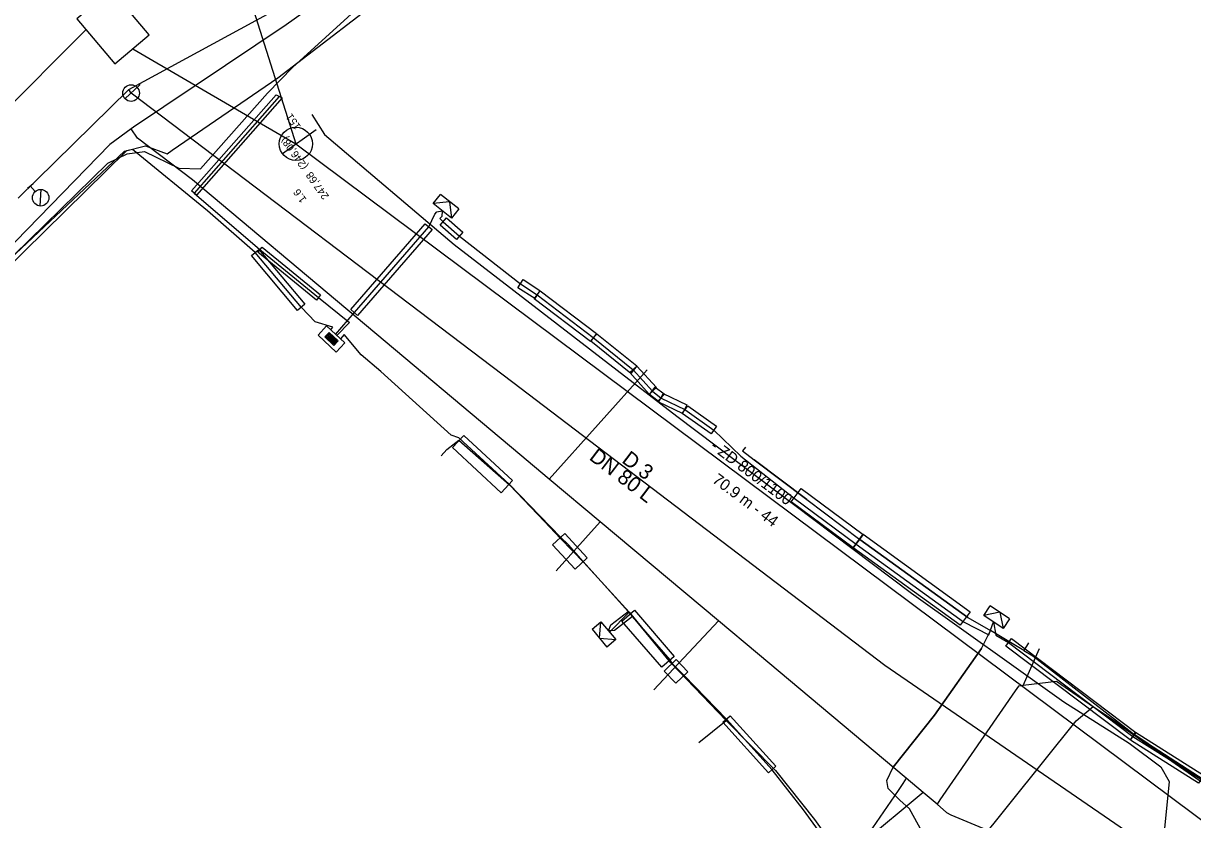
# Model space of a CAD drawing. Extents: x -600636 to -600148, y -1203980 to -1203569.
# Drawn here: x -600384.3 to -600313.9, y -1203678.1 to -1203630.1 of the extents above; entities that cross this region are included whole.
import ezdxf

# ---------------------------------------------------------------- set-up
doc = ezdxf.new("R2010")
doc.units = 0
for name, color, linetype in [('Cetin zam průběh', 7, 'Continuous'), ('EON objekty', 7, 'Continuous'), ('EON podzemní NN', 7, 'Continuous'), ('EON podzemní VN', 7, 'Continuous'), ('GasNet NTL', 7, 'Continuous'), ('Implicitní', 7, 'Continuous'), ('VaK Břeclav_kanalizace', 7, 'Continuous'), ('VaK Břeclav_kanalizace_popis', 7, 'Continuous'), ('Vak Břeclav_vodovod', 7, 'Continuous'), ('Vak Břeclav_vodovod_popis', 7, 'Continuous'), ('Vrstva 9', 7, 'Continuous')]:
    doc.layers.add(name, color=color, linetype=linetype)

# ---------------------------------------------------------------- blocks, each defined once
blk = doc.blocks.new('NN630')
at = {"layer": 'Vrstva 9'}
for points in [[(-0.003, -0.7), (-0.703, 0)], [(-0.703, -0.7), (-0.703, 0), (0.697, 0), (0.697, -0.7)], [(-0.703, -0.7), (0.697, -0.7)], [(-0.003, -0.7), (0.697, 0)]]:
    blk.add_lwpolyline(points, dxfattribs=at)
blk = doc.blocks.new('NN620')
at = {"layer": 'EON objekty'}
for points in [[(0.752, 0.004), (-0.748, 0.004)], [(-0.748, 0.004), (-0.748, -0.746)], [(0.752, -0.746), (0.752, 0.004)], [(0.368, -0.18), (-0.376, -0.18)], [(-0.376, -0.18), (-0.376, -0.558)], [(-0.376, -0.558), (0.368, -0.558)], [(0.321, -0.227), (-0.329, -0.227)], [(-0.329, -0.227), (-0.329, -0.51)], [(-0.329, -0.51), (0.321, -0.51)], [(0.274, -0.274), (-0.281, -0.274)], [(-0.281, -0.274), (-0.281, -0.463)], [(-0.281, -0.463), (0.274, -0.463)], [(0.227, -0.321), (-0.234, -0.321)], [(-0.234, -0.321), (-0.234, -0.416)], [(-0.234, -0.416), (0.227, -0.416)], [(-0.193, -0.369), (0.185, -0.369)], [(0.227, -0.416), (0.227, -0.321)], [(0.274, -0.463), (0.274, -0.274)], [(0.321, -0.51), (0.321, -0.227)], [(0.368, -0.558), (0.368, -0.18)], [(-0.748, -0.746), (0.752, -0.746)]]:
    blk.add_lwpolyline(points, dxfattribs=at)
blk = doc.blocks.new('MoSymbol 2')
at = {"layer": 'Implicitní'}
blk.add_line((0, 0.0005), (0, -0.00075), dxfattribs=at)
blk.add_circle((0, 0), 0.0005, dxfattribs=at)
blk = doc.blocks.new('MoSymbol 3')
at = {"layer": 'Implicitní'}
for p, q in [((-0.000225, 0.00095), (0.000225, 0.00095)), ((0, 0.00095), (0, 0.0005)), ((-0.000365, -0.000365), (0.000365, 0.000365))]:
    blk.add_line(p, q, dxfattribs=at)
blk.add_circle((0, 0), 0.0005, dxfattribs=at)

msp = doc.modelspace()

# ---------------------------------------------------------------- linework, layer by layer
at = {"layer": 'Cetin zam průběh'}
for points in [[(-600403.75, -1203662.4), (-600400.59, -1203659.29), (-600391.04, -1203649.83), (-600378.25, -1203637.79), (-600376.97, -1203637.47), (-600375.66, -1203637.95), (-600375.36, -1203637.74), (-600369.01, -1203633.38), (-600361.52, -1203627.61), (-600348.82, -1203618.06), (-600335.53, -1203608.82), (-600318.11, -1203596.27), (-600313.64, -1203592.14)], [(-600368.09, -1203632.74), (-600363.25, -1203628.32)], [(-600385.87, -1203644.99), (-600379.24, -1203638.53), (-600378.07, -1203637.95), (-600377.04, -1203637.82), (-600374.96, -1203638.83), (-600373.66, -1203638.86), (-600369.62, -1203634.3), (-600368.09, -1203632.74)], [(-600375.36, -1203637.74), (-600369.01, -1203633.38)], [(-600373.66, -1203638.86), (-600369.62, -1203634.3)], [(-600359.16, -1203656.16), (-600358.81, -1203655.77), (-600358.09, -1203655.2), (-600355.04, -1203657.89), (-600352.93, -1203660.11), (-600351.96, -1203661.13), (-600350.57, -1203662.57), (-600347.84, -1203665.57)], [(-600358.09, -1203655.2), (-600355.04, -1203657.89)], [(-600340.82, -1203655.62), (-600341, -1203655.85), (-600340.3, -1203656.39), (-600337.13, -1203658.78), (-600333.94, -1203661.19), (-600327.42, -1203665.89), (-600326.06, -1203666.68)], [(-600337.13, -1203658.78), (-600340.3, -1203656.39)], [(-600351.96, -1203661.13), (-600350.57, -1203662.57)], [(-600327.42, -1203665.89), (-600333.94, -1203661.19)], [(-600349.03, -1203666.79), (-600347.84, -1203665.57)], [(-600347.84, -1203665.57), (-600345.32, -1203668.62)], [(-600341.99, -1203672.1), (-600345.32, -1203668.62), (-600347.84, -1203665.57)], [(-600331.52, -1203676.9), (-600332.22, -1203676.19), (-600332.3, -1203675.71), (-600331.92, -1203674.9), (-600329.44, -1203671.78), (-600326.6, -1203667.76), (-600326.06, -1203666.68)], [(-600324.05, -1203667.87), (-600326.06, -1203666.68)], [(-600323.77, -1203667.42), (-600324.05, -1203667.87)], [(-600326.6, -1203667.76), (-600329.44, -1203671.78), (-600331.92, -1203674.9)], [(-600324.05, -1203667.87), (-600323.52, -1203668.21), (-600317.28, -1203673.02), (-600311.48, -1203676.78)], [(-600323.52, -1203668.21), (-600317.28, -1203673.02)], [(-600329.02, -1203689.27), (-600327.65, -1203686.16), (-600327.07, -1203683.69), (-600326.94, -1203681.95), (-600327.13, -1203680.22), (-600326.9, -1203679.6), (-600320.9, -1203672.11), (-600319.87, -1203671.25), (-600312.14, -1203676.45), (-600307.68, -1203679.27), (-600299.7, -1203684.11), (-600292.77, -1203688.32), (-600284.45, -1203693.32), (-600273.46, -1203699.98), (-600262.73, -1203706.4), (-600257.97, -1203709.2), (-600243.31, -1203717.93), (-600240.56, -1203720.13), (-600238.73, -1203718.32)], [(-600343.64, -1203673.42), (-600341.99, -1203672.1)], [(-600341.99, -1203672.1), (-600339.02, -1203675.1)], [(-600341.99, -1203672.1), (-600339.02, -1203675.1), (-600336.67, -1203678.06), (-600335.49, -1203679.73), (-600334.6, -1203680.94), (-600332.38, -1203684.29), (-600330.34, -1203687.27), (-600329.66, -1203687.89)], [(-600329.66, -1203687.89), (-600329.92, -1203686.15), (-600329.28, -1203683.93), (-600328.92, -1203681.87), (-600329, -1203680.95), (-600330.94, -1203677.41), (-600331.52, -1203676.9)]]:
    msp.add_lwpolyline(points, dxfattribs=at)
at = {"layer": 'EON podzemní NN'}
for points in [[(-600369.107, -1203634.396), (-600368.748, -1203634.595), (-600368.748, -1203634.595), (-600373.899, -1203640.453), (-600374.2, -1203640.188)], [(-600359.216, -1203642.251), (-600358.833, -1203641.82), (-600357.859, -1203642.686), (-600358.243, -1203643.117)], [(-600360.118, -1203642.173), (-600359.712, -1203642.525), (-600364.197, -1203647.69), (-600364.6, -1203647.341)], [(-600370.59, -1203644.082), (-600370.152, -1203643.715), (-600367.372, -1203647.024), (-600367.812, -1203647.394)], [(-600369.954, -1203643.575), (-600366.423, -1203646.455), (-600366.676, -1203646.765), (-600370.207, -1203643.885)], [(-600354.533, -1203646.022), (-600354.217, -1203645.538), (-600353.207, -1203646.198), (-600353.522, -1203646.681)], [(-600353.548, -1203646.691), (-600353.191, -1203646.221), (-600349.803, -1203648.791), (-600350.16, -1203649.261)], [(-600350.151, -1203649.253), (-600349.786, -1203648.798), (-600347.372, -1203650.733), (-600347.738, -1203651.189)], [(-600347.794, -1203651.139), (-600347.366, -1203650.751), (-600346.195, -1203652.04), (-600346.624, -1203652.43)], [(-600346.606, -1203652.464), (-600346.257, -1203652.011), (-600345.732, -1203652.415), (-600346.082, -1203652.868)], [(-600346.042, -1203652.91), (-600345.786, -1203652.388), (-600344.357, -1203653.089), (-600344.612, -1203653.61)], [(-600344.638, -1203653.601), (-600344.306, -1203653.13), (-600342.564, -1203654.357), (-600342.896, -1203654.828)], [(-600358.474, -1203655.658), (-600357.794, -1203654.927), (-600354.871, -1203657.644), (-600355.553, -1203658.376)], [(-600338.073, -1203658.917), (-600337.478, -1203658.113), (-600333.74, -1203660.889), (-600334.333, -1203661.688)], [(-600351.089, -1203662.981), (-600352.449, -1203661.51), (-600351.713, -1203660.831), (-600350.355, -1203662.302)], [(-600334.326, -1203661.687), (-600333.733, -1203660.87), (-600327.293, -1203665.553), (-600327.881, -1203666.362)], [(-600348.277, -1203666.113), (-600347.521, -1203665.458), (-600345.117, -1203668.235), (-600345.873, -1203668.89)], [(-600325.136, -1203667.608), (-600324.793, -1203667.153), (-600317.304, -1203672.819), (-600317.64, -1203673.263)], [(-600345.716, -1203669.119), (-600344.993, -1203668.428), (-600344.288, -1203669.165), (-600345.011, -1203669.856)], [(-600342.193, -1203672.206), (-600341.753, -1203671.806), (-600339.003, -1203674.851), (-600339.437, -1203675.243)], [(-600317.616, -1203673.271), (-600317.317, -1203672.8), (-600313.236, -1203675.395), (-600313.532, -1203675.861)]]:
    msp.add_lwpolyline(points, close=True, dxfattribs=at)
for points in [[(-600368.927, -1203634.495), (-600374.05, -1203640.32), (-600370.08, -1203643.73), (-600366.55, -1203646.61), (-600364.68, -1203648.12), (-600365.448, -1203648.9)], [(-600365.812, -1203648.565), (-600365.681, -1203648.403), (-600366.76, -1203648.07), (-600367.58, -1203647.21), (-600370.36, -1203643.9), (-600373.24, -1203641.39), (-600377.75, -1203637.7), (-600378.11, -1203637.77), (-600385.513, -1203645.048)], [(-600365.519, -1203648.839), (-600364.39, -1203647.52), (-600359.91, -1203642.35), (-600359.54, -1203641.598), (-600359.414, -1203641.455), (-600359.09, -1203641.39), (-600359.12, -1203641.727), (-600359.24, -1203641.863), (-600359.03, -1203642.05), (-600358.06, -1203642.92), (-600354.39, -1203645.79), (-600353.38, -1203646.45), (-600350, -1203649.03), (-600347.59, -1203650.97), (-600346.42, -1203652.26), (-600345.9, -1203652.67), (-600344.47, -1203653.37), (-600342.73, -1203654.6), (-600341.114, -1203656.177), (-600337.892, -1203658.699), (-600334.149, -1203661.481), (-600327.695, -1203666.161), (-600326.17, -1203666.939), (-600325.88, -1203666.16), (-600325.749, -1203666.954), (-600324.98, -1203667.4), (-600317.48, -1203673.05), (-600313.39, -1203675.63)], [(-600334.77, -1203681), (-600337.32, -1203677.47), (-600339.22, -1203675.06), (-600341.977, -1203672.021), (-600344.526, -1203669.391), (-600345.213, -1203668.675), (-600345.36, -1203668.449), (-600347.63, -1203665.83), (-600348.726, -1203666.671), (-600349.08, -1203666.69), (-600348.944, -1203666.334), (-600347.896, -1203665.529), (-600350.6, -1203662.52), (-600351.494, -1203661.523), (-600351.96, -1203661.043), (-600355.061, -1203657.866), (-600358.09, -1203655.066), (-600358.55, -1203654.911), (-600362.8, -1203651.07), (-600363.99, -1203650.06), (-600365.009, -1203648.842), (-600365.226, -1203649.112)]]:
    msp.add_lwpolyline(points, dxfattribs=at)
at = {"layer": 'EON podzemní VN'}
msp.add_lwpolyline([(-600366.95, -1203635.593), (-600366.181, -1203636.795), (-600358.381, -1203643.411), (-600344.954, -1203653.759), (-600330.827, -1203664.425), (-600321.645, -1203670.963), (-600317.713, -1203673.458), (-600315.791, -1203674.896), (-600315.293, -1203675.777), (-600315.944, -1203682.246), (-600316.226, -1203683.581), (-600322.501, -1203693.042), (-600331.079, -1203704.985), (-600348.911, -1203730.288), (-600354.208, -1203737.743), (-600361.516, -1203748.136), (-600365.138, -1203753.003), (-600368.824, -1203758.254), (-600375.091, -1203769.039), (-600381.398, -1203780.278), (-600382.49, -1203782.6), (-600383.25, -1203783.59)], dxfattribs=at)
at = {"layer": 'GasNet NTL'}
for points in [[(-600363.908, -1203626.786), (-600366.43, -1203628.72), (-600368.49, -1203630.18), (-600377.69, -1203636.35), (-600377.83, -1203636.45), (-600379.12, -1203637.4), (-600390.52, -1203649.08), (-600393.75, -1203652.39), (-600407.12, -1203666.06), (-600410.69, -1203669.71), (-600416.55, -1203675.06), (-600425.93, -1203683.63), (-600443.216, -1203700.032), (-600443.404, -1203700.211), (-600447.923, -1203704.499), (-600448.05, -1203704.619)], [(-600329.27, -1203677.14), (-600330.12, -1203676.43), (-600331.14, -1203675.57), (-600340.09, -1203668.06), (-600342.45, -1203666.09), (-600349.58, -1203660.13), (-600352.66, -1203657.56), (-600354.43, -1203656.08), (-600374.14, -1203639.53), (-600377.45, -1203637.01), (-600377.83, -1203636.45)], [(-600352.66, -1203657.56), (-600346.75, -1203650.97)], [(-600352.23, -1203663.07), (-600349.58, -1203660.13)], [(-600346.34, -1203670.24), (-600342.45, -1203666.09)], [(-600324.1, -1203669.99), (-600323.1, -1203667.75)], [(-600309.24, -1203678.67), (-600322.08, -1203669.74), (-600324.1, -1203669.99), (-600324.38, -1203670.02), (-600324.57, -1203670.3), (-600329.11, -1203676.87), (-600329.27, -1203677.14), (-600328.72, -1203677.64), (-600328.46, -1203677.78), (-600313.71, -1203683.92)], [(-600331.14, -1203675.57), (-600331.35, -1203675.9), (-600331.63, -1203676.31)], [(-600331.63, -1203676.31), (-600333.84, -1203679.52), (-600334.07, -1203679.86), (-600334.63, -1203680.67), (-600332.29, -1203684.08), (-600331.07, -1203685.85), (-600329.31, -1203687.34), (-600321.69, -1203692.03)], [(-600330.12, -1203676.43), (-600333.84, -1203679.52), (-600334.14, -1203679.77)]]:
    msp.add_lwpolyline(points, dxfattribs=at)
at = {"layer": 'VaK Břeclav_kanalizace'}
for p, q in [((-600373.126, -1203620.905), (-600367.912, -1203637.359)), ((-600421.971, -1203671.963), (-600380.571, -1203630.481)), ((-600377.747, -1203631.629), (-600367.912, -1203637.359)), ((-600367.912, -1203637.359), (-600311.102, -1203679.776))]:
    msp.add_line(p, q, dxfattribs=at)
msp.add_lwpolyline([(-600380.107, -1203626.821), (-600381.1, -1203627.66), (-600380.127, -1203628.993), (-600381.12, -1203629.832), (-600378.829, -1203632.544), (-600376.754, -1203630.791)], close=True, dxfattribs=at)
at = {"layer": 'Vak Břeclav_vodovod'}
for p, q in [((-600377.983, -1203634.082), (-600365.168, -1203627.107)), ((-600384.65, -1203640.632), (-600377.983, -1203634.082)), ((-600377.846, -1203634.299), (-600377.983, -1203634.082))]:
    msp.add_line(p, q, dxfattribs=at)
msp.add_lwpolyline([(-600316.256, -1203679.894), (-600332.434, -1203668.792), (-600354.837, -1203651.734), (-600377.846, -1203634.299)], dxfattribs=at)

# ---------------------------------------------------------------- block references
at = {"layer": 'EON podzemní NN'}
for name, p, rotation in [('NN630', (-600359.09, -1203641.39), 141.80983611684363), ('NN620', (-600365.52, -1203648.84), -42.98922773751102), ('NN630', (-600325.88, -1203666.16), 146.63981950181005), ('NN630', (-600349.08, -1203666.69), -50.01474170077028)]:
    msp.add_blockref(name, p, dxfattribs=dict(at, rotation=rotation))
at = {"layer": 'VaK Břeclav_kanalizace', "xscale": 1999.750031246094, "yscale": 1999.7500312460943, "rotation": 125.4179044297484}
msp.add_blockref('MoSymbol 2', (-600367.912, -1203637.359), dxfattribs=at)
at = {"layer": 'Vak Břeclav_vodovod', "xscale": 999.875015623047}
for name, p, yscale, rotation in [('MoSymbol 2', (-600377.846, -1203634.299), 999.875015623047, 132.556395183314), ('MoSymbol 3', (-600383.292, -1203640.604), 999.8750156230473, 41.15293018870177)]:
    msp.add_blockref(name, p, dxfattribs=dict(at, yscale=yscale, rotation=rotation))

# ---------------------------------------------------------------- texts
at = {"layer": 'VaK Břeclav_kanalizace_popis'}
for s, height, rotation, p in [('151', 0.4549, 125.4179, (-600367.592, -1203636.309)), ('247,68  (246,08)', 0.45494, 125.4179, (-600365.897, -1203640.508)), ('1.6', 0.4549, 125.4179, (-600367.246, -1203640.71)), ('- ZD 800/1100', 0.68241, 323.25327, (-600342.996, -1203655.68)), ('70.9 m - 44', 0.68241, 323.25327, (-600342.871, -1203657.708))]:
    msp.add_text(s, height=height, rotation=rotation, dxfattribs=at).set_placement(p)
at = {"layer": 'Vak Břeclav_vodovod_popis'}
for s, p in [('DN 80 L', (-600350.296, -1203656.335)), ('D 3', (-600348.331, -1203656.511))]:
    msp.add_text(s, height=0.9099, rotation=322.71378, dxfattribs=at).set_placement(p)

doc.saveas('drawing.dxf')
